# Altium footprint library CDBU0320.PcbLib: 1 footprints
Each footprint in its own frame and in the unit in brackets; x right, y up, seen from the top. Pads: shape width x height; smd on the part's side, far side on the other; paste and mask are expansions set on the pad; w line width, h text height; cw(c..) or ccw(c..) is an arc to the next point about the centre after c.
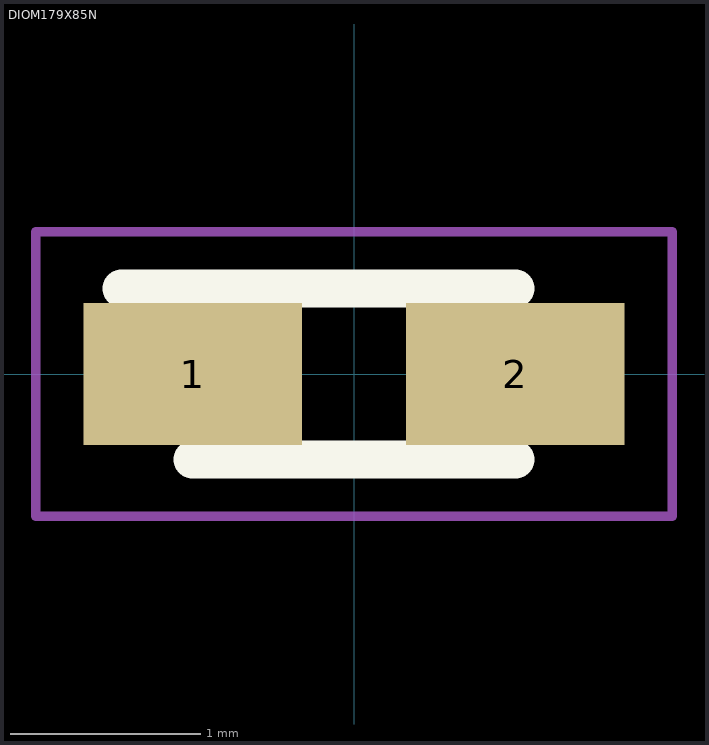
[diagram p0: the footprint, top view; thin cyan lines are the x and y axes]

## DIOM179X85N [mm]
pads (2):
  rect 1.15x0.75 smd: 1(-0.85,0) 2(0.85,0)
Top Overlay:
  lines w0.2: -1.225,0.45 0.85,0.45 ; -0.85,-0.45 0.85,-0.45
Mechanical 15:
  lines w0.1: -0.85,0.075 -0.475,0.45 ; -0.85,-0.45 0.85,-0.45 0.85,0.45 -0.85,0.45 -0.85,-0.45
Mechanical 20:
  lines w0.05: -1.675,-0.75 1.675,-0.75 1.675,0.75 -1.675,0.75 -1.675,-0.75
